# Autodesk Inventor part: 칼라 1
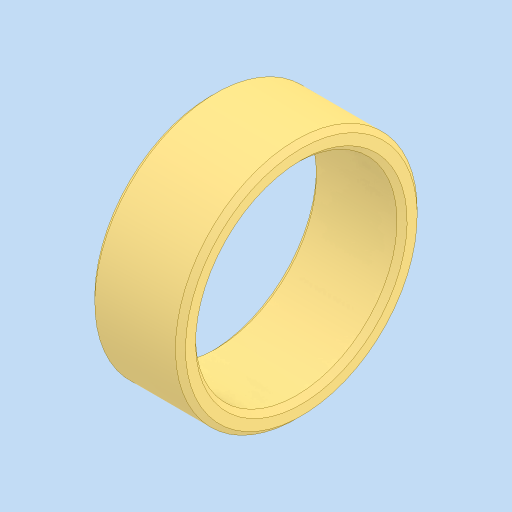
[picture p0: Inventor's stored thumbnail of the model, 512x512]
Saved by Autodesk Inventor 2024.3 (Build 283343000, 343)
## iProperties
Created: 2025-11
Part Number: 칼라 1
Material: 강철, 연강
Document SubType Name: Modeling
Designer: PC2-03
Density: 7.85 g/cm^3
Appearance: 기본값
Author: jhkim
Sending System: Autodesk Inventor 2026
Preprocessor: ST-DEVELOPER v20.1
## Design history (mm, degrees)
feature "솔리드1"
node "솔리드2"
